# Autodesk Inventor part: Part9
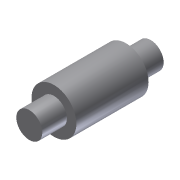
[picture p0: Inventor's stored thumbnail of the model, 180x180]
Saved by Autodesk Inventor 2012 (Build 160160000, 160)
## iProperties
Shininess: 77.0
Length Units: 11269
Angle Units: 11279
Time Units: 11290
Mass Units: 11283
Length Display Precision: 3
Angle Display Precision: 2
Created: 2002-01
Part Number: Part9
Document SubType Name: Modeling
Designer: ***
Density: 1 g/cm^3
Material: Default
Density: 0.0
Volumn: 0.0
Area: 0.0
PropertySet Name: Model Information
Control State: 0
Master: False
Checked Out: False
Author: ***
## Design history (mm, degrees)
sketch "Sketch1"
  geometry: L1 (0.279, 23.245)-(5.19, 23.245); L2 (5.19, 23.245)-(5.19, 13.947); L3 (5.19, 13.947)-(8.761, 13.947); L4 (8.761, 13.947)-(8.761, -13.295); L5 (8.761, -13.295)-(5.19, -13.295); L6 (5.19, -13.295)-(5.19, -22.592); L7 (5.19, -22.592)-(0.279, -22.592); L8 (0.279, -22.592)-(0.279, 23.245)
  constraints: 16 end point, 5 parallel, 2 equal length, 1 collinear, 1 horizontal, 1 perpendicular
revolve "Revolution1" sketch "Sketch1" stored, may be unused: angle "d0" = 90 deg
body "Solid1"
